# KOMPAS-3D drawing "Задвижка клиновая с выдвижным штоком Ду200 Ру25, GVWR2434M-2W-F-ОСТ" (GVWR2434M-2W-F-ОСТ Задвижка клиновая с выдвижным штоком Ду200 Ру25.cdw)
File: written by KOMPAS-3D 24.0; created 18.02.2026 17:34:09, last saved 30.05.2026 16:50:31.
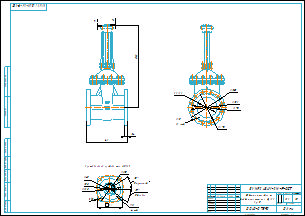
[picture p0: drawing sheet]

Document properties: Автор: R2D2; Форматы листов документа: A2; Полное имя файла: GVWR2434M-2W-F-ОСТ Задвижка клиновая с выдвижным штоком Ду200 Ру25.m3d; Масса: 100; Наименование: Задвижка клиновая с выдвижным штоком Ду200 Ру25; Количество листов документа: 1; Примечание: D040-07590

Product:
- Part/product: Задвижка клиновая с выдвижным штоком Ду200 Ру25  | designation GVWR2434M-2W-F-ОСТ
    Масса: 100
    Раздел спецификации: Прочие изделия
    Примечание: D040-07590

Views: Проекционный вид 2
Referenced files in E:\Работа\Зайцев\Для компаса\: чертеж DN.ru А3.cdt
Referenced files in E:\Работа\Зайцев\GVWR2434M-2W-F-ОСТ Задвижка клиновая с выдвижным штоком DN.ru Ду50-300 Ру25\исходные материалы\DN200\DN200\: GVWR2434M-2W-F-ОСТ Задвижка клиновая с выдвижным штоком Ду200 Ру25.m3d
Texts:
  Присоединение привода тип АК (Б)
  чертеж DN.ru А3.cdt
  Задвижка клиновая с
  выдвижным штоком Ду200
  Ру25
  GVWR2434M-2W-F-ОСТ
  Задвижка клиновая с выдвижным штоком Ду200 Ру25
  GVWR2434M-2W-F-ОСТ Задвижка клиновая с выдвижным штоком Ду200 Ру25
Dimensions and other numbers on the sheet: 108; 45; 58; 135; 13; 12; 4 отв.; 122; 5 впадин; 5 кулачков; 1:5; 0; 1; 2; 100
